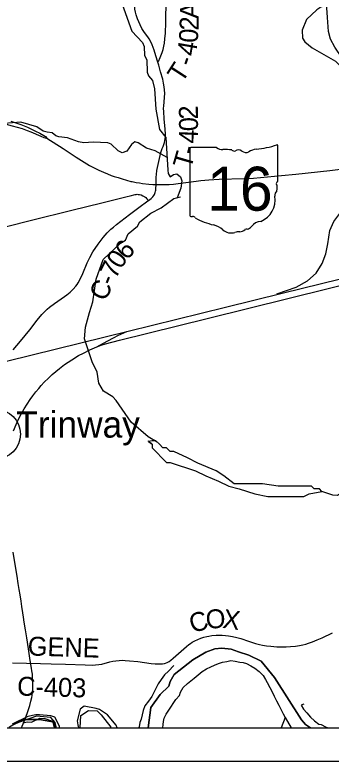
# Model space of a CAD drawing. Extents: x 0 to 34, y 0 to 22.
# Drawn here: x 6.577 to 7.523, y 14 to 16.238 of the extents above; entities that cross this region are included whole.
import ezdxf

# ---------------------------------------------------------------- set-up
doc = ezdxf.new("R2010")
doc.units = 0
for name, color, linetype in [('GM_X_Corporation', 7, 'Continuous'), ('GM_X_County_Road', 7, 'Continuous'), ('GM_X_County_Road_Text', 7, 'Continuous'), ('GM_X_Major_River', 7, 'Continuous'), ('GM_X_Minor_Lake', 7, 'Continuous'), ('GM_X_Minor_River', 7, 'Continuous'), ('GM_X_Rail_Line', 7, 'Continuous'), ('GM_X_State_Location', 7, 'Continuous'), ('GM_X_State_Route', 7, 'Continuous'), ('GM_X_State_Shield', 7, 'Continuous'), ('GM_X_Township_Road', 7, 'Continuous'), ('GM_X_Township_Road_Text', 7, 'Continuous'), ('GM_X_Unincorporated', 7, 'Continuous'), ('GM_X_Unincorporated_Text', 7, 'Continuous'), ('SH_Data', 7, 'Continuous')]:
    doc.layers.add(name, color=color, linetype=linetype)

msp = doc.modelspace()

# ---------------------------------------------------------------- linework, layer by layer
at = {"layer": 'GM_X_Corporation'}
for points in [[(2.1, 16.4477), (2.1, 14.1), (8.9, 14.1), (8.9, 16.2485)], [(6.5592, 14.1021), (6.5997, 14.1245), (6.6505, 14.1251), (6.6949, 14.1163), (6.697, 14.1), (6.7725, 14.1), (6.774, 14.1364), (6.7969, 14.1517), (6.8227, 14.1507), (6.8352, 14.1392), (6.8644, 14.1013), (6.8648, 14.1), (6.9761, 14.1), (6.9834, 14.1608), (7.0113, 14.1998), (7.0381, 14.2242), (7.0417, 14.2386), (7.0533, 14.2599), (7.11, 14.3032), (7.1487, 14.3269), (7.1751, 14.337), (7.1967, 14.339), (7.2239, 14.3354), (7.246, 14.328), (7.277, 14.3176), (7.3146, 14.2996), (7.3543, 14.251), (7.4347, 14.1238), (7.4466, 14.1098), (7.4614, 14.1), (7.7766, 14.1)], [(5.9661, 14.1), (6.701, 14.1), (6.6974, 14.116), (6.6847, 14.1303), (6.6414, 14.1352), (6.5874, 14.1159), (6.568, 14.1068)], [(5.9669, 14.1), (6.697, 14.1), (6.6949, 14.1163), (6.6505, 14.1251), (6.5997, 14.1245), (6.5592, 14.1021)]]:
    msp.add_lwpolyline(points, dxfattribs=at)
msp.add_lwpolyline([(6.9761, 14.1), (7.4614, 14.1), (7.4466, 14.1098), (7.4347, 14.1238), (7.3543, 14.251), (7.3146, 14.2996), (7.277, 14.3176), (7.246, 14.328), (7.2239, 14.3354), (7.1967, 14.339), (7.1751, 14.337), (7.1487, 14.3269), (7.11, 14.3032), (7.0533, 14.2599), (7.0417, 14.2386), (7.0381, 14.2242), (7.0113, 14.1998), (6.9834, 14.1608)], close=True, dxfattribs=at)
at = {"layer": 'GM_X_County_Road'}
for points in [[(6.9773, 15.6816), (6.9848, 15.6877), (6.9894, 15.6923), (6.9925, 15.6961), (6.9945, 15.6991), (6.9956, 15.7021), (6.9968, 15.7054), (6.9979, 15.7096), (6.9984, 15.712), (6.999, 15.7169), (6.9995, 15.7293)], [(6.0536, 15.5319), (6.1339, 15.5298), (6.1992, 15.5286), (6.2241, 15.529), (6.2458, 15.5306), (6.2674, 15.5335), (6.2888, 15.5378), (6.3973, 15.5647), (6.6263, 15.6221), (6.7469, 15.6522), (6.8373, 15.6746), (6.913, 15.6935)], [(6.913, 15.6935), (6.9217, 15.6956), (6.9368, 15.6992), (6.9399, 15.6997), (6.9429, 15.7), (6.9461, 15.6999), (6.9499, 15.6993), (6.9547, 15.698), (6.9603, 15.6957), (6.9655, 15.6927), (6.9684, 15.6902), (6.9722, 15.6867), (6.9773, 15.6816)], [(6.5714, 15.2339), (6.5935, 15.2599), (6.6212, 15.2932), (6.6438, 15.3228), (6.6576, 15.3396), (6.662, 15.3446), (6.6684, 15.3508), (6.6734, 15.3553), (6.6801, 15.3611), (6.6951, 15.3722), (6.7256, 15.3935), (6.7324, 15.3987), (6.7425, 15.407), (6.7514, 15.4155), (6.7594, 15.4248), (6.7629, 15.4296), (6.7664, 15.4349), (6.7723, 15.4457), (6.78, 15.4626), (6.7931, 15.4941), (6.8013, 15.5109), (6.8106, 15.5271), (6.8263, 15.5502), (6.8412, 15.5701), (6.8534, 15.5842), (6.8583, 15.5894), (6.8645, 15.5952), (6.8716, 15.6012), (6.881, 15.6093), (6.9201, 15.6399), (6.9474, 15.6604), (6.9753, 15.68), (6.9773, 15.6816)], [(6.57, 14.295), (6.6539, 14.2926), (6.6849, 14.2917), (6.7285, 14.2904), (6.7875, 14.2884), (6.8092, 14.2879), (6.8185, 14.2882), (6.8277, 14.2893), (6.8367, 14.2911), (6.8608, 14.2974), (6.8699, 14.2995), (6.8792, 14.3011), (6.8885, 14.302), (6.8979, 14.3023), (6.9073, 14.3021), (6.9197, 14.3011), (6.9444, 14.2982), (6.9845, 14.293), (6.9969, 14.2919), (7.0061, 14.2914), (7.0123, 14.2915), (7.0184, 14.292), (7.0244, 14.2931), (7.0274, 14.2939), (7.033, 14.2961), (7.0384, 14.299), (7.0435, 14.3024), (7.0507, 14.3082), (7.0903, 14.3432), (7.0975, 14.3492), (7.1025, 14.353), (7.1077, 14.3564), (7.116, 14.361), (7.1245, 14.3649), (7.1332, 14.3683), (7.1421, 14.3713), (7.1512, 14.3738), (7.1573, 14.375), (7.1666, 14.3763), (7.1791, 14.3773), (7.1884, 14.3777), (7.1978, 14.3776), (7.2072, 14.3771), (7.2165, 14.376), (7.2288, 14.3739), (7.241, 14.3711), (7.253, 14.3676), (7.2766, 14.3598), (7.2972, 14.353), (7.3091, 14.3495), (7.3182, 14.3475), (7.3304, 14.3455), (7.3427, 14.3442), (7.3613, 14.343), (7.3768, 14.3425), (7.3892, 14.3427), (7.4016, 14.3435), (7.417, 14.3451), (7.4293, 14.3469), (7.4384, 14.3487), (7.4474, 14.3509), (7.4563, 14.3535), (7.468, 14.3576), (7.4823, 14.3635), (7.4965, 14.3697), (7.5273, 14.3847)]]:
    msp.add_lwpolyline(points, dxfattribs=at)
at = {"layer": 'GM_X_Major_River'}
for points in [[(7.0528, 14.2867), (7.0364, 14.27), (7.0251, 14.2582), (7.0149, 14.2449), (7.0062, 14.2312), (7.0006, 14.2217), (6.9942, 14.2073), (6.9863, 14.194), (6.9769, 14.1796), (6.9663, 14.1655), (6.9607, 14.1515), (6.9577, 14.1386), (6.9551, 14.1257), (6.951, 14.1158), (6.9487, 14.1025), (6.9483, 14.1)], [(7.0589, 14.1845), (7.0693, 14.1964), (7.0725, 14.2066), (7.0807, 14.2208), (7.0934, 14.2331), (7.1031, 14.2408), (7.1132, 14.2482), (7.1252, 14.2589), (7.1371, 14.269), (7.1503, 14.2767), (7.1634, 14.283), (7.1747, 14.2877), (7.1864, 14.2928), (7.1981, 14.2967), (7.2113, 14.2984), (7.2234, 14.3016), (7.2366, 14.2995), (7.2503, 14.2971), (7.2605, 14.2953), (7.27, 14.2924), (7.2834, 14.2858), (7.2956, 14.2788), (7.3079, 14.2691), (7.3198, 14.2571), (7.3271, 14.2451), (7.3326, 14.2353), (7.34, 14.2206), (7.3466, 14.2074), (7.3528, 14.195), (7.3598, 14.1811), (7.3672, 14.1675), (7.3735, 14.1559), (7.3801, 14.1416), (7.3863, 14.1303), (7.3933, 14.1183), (7.4041, 14.1)], [(7.0199, 14.1), (7.0206, 14.1096), (7.0221, 14.119), (7.024, 14.1289), (7.0296, 14.1407), (7.0379, 14.1528), (7.0589, 14.1845)], [(7.4418, 14.1709), (7.4342, 14.1677), (7.4412, 14.1557), (7.4512, 14.1445), (7.4616, 14.1317), (7.4743, 14.1205), (7.4869, 14.1112)], [(7.4869, 14.1112), (7.4941, 14.1098), (7.5067, 14.1032), (7.5141, 14.1)]]:
    msp.add_lwpolyline(points, dxfattribs=at)
at = {"layer": 'GM_X_Minor_Lake'}
for points in [[(7.0526, 14.9285), (7.0418, 14.9285), (7.031, 14.9393), (7.0202, 14.9393), (7.0094, 14.9501), (6.9986, 14.9609), (6.9878, 14.9609), (6.977, 14.9587)], [(6.977, 14.9587), (6.977, 14.9609), (6.9878, 14.9501), (6.9878, 14.9393), (6.9986, 14.9285), (7.0202, 14.9069), (7.031, 14.8961), (7.0418, 14.8961)], [(6.977, 14.9587), (6.9878, 14.9501), (6.9878, 14.9393), (6.9986, 14.9285), (7.0202, 14.9069), (7.031, 14.8961), (7.0418, 14.8961)], [(7.4961, 14.8089), (7.4884, 14.8166), (7.4729, 14.8166), (7.4652, 14.8244), (7.442, 14.8244), (7.4265, 14.8244), (7.4033, 14.8244), (7.3647, 14.8244), (7.3182, 14.8321), (7.2796, 14.8321), (7.2332, 14.8321), (7.2022, 14.8553), (7.179, 14.8708), (7.1249, 14.894), (7.0939, 14.9095), (7.0526, 14.9285)], [(7.0418, 14.8961), (7.1172, 14.8708), (7.1481, 14.8553), (7.1868, 14.8399), (7.2177, 14.8244), (7.2486, 14.8166), (7.295, 14.8012), (7.3337, 14.7934), (7.3879, 14.7934), (7.4111, 14.7934), (7.4343, 14.7934), (7.442, 14.7934), (7.4575, 14.8012), (7.4961, 14.8089)]]:
    msp.add_lwpolyline(points, dxfattribs=at)
at = {"layer": 'GM_X_Minor_River'}
msp.add_line((7.3861, 14.1307), (7.3736, 14.1), dxfattribs=at)
for points in [[(6.8721, 16.3002), (6.8979, 16.2707), (6.927, 16.1892), (6.9589, 16.1552), (6.9643, 16.1431), (6.9652, 16.1161), (6.972, 16.1036), (6.9726, 16.0668), (6.9772, 16.0558), (6.989, 16.0415), (6.9944, 16.0164), (6.9984, 15.9558), (7.0093, 15.8947), (7.0291, 15.8709), (7.0344, 15.7726), (7.036, 15.7624), (7.0421, 15.7522)], [(7.5143, 16.286), (7.5155, 16.2768), (7.5069, 16.2654), (7.4929, 16.2615), (7.4805, 16.2539), (7.4497, 16.2244), (7.4371, 16.1929), (7.4374, 16.1682), (7.4446, 16.1573), (7.4671, 16.1392), (7.537, 16.0999), (7.548, 16.0886), (7.5657, 16.0595), (7.5876, 16.0115), (7.5901, 15.9831), (7.5944, 15.971), (7.5938, 15.9486), (7.6112, 15.9063), (7.6182, 15.876)], [(7.0323, 15.8104), (6.9971, 15.8306), (6.9709, 15.8388), (6.9462, 15.8543), (6.9356, 15.8573), (6.9258, 15.8497), (6.9123, 15.8299), (6.8975, 15.8245), (6.8861, 15.8306), (6.8652, 15.8502), (6.8554, 15.854), (6.8111, 15.8565), (6.7827, 15.8545), (6.7668, 15.8571), (6.7338, 15.8699), (6.7084, 15.8728), (6.6989, 15.8758), (6.6879, 15.8849), (6.6731, 15.886), (6.661, 15.8897), (6.6424, 15.9026), (6.5943, 15.9161), (6.5447, 15.9125)], [(7.042, 15.7523), (7.0517, 15.7598), (7.0615, 15.7614), (7.0729, 15.7528), (7.0768, 15.7403), (7.0739, 15.7186), (7.0622, 15.6896)], [(7.003, 14.9566), (6.9762, 14.9723), (6.9249, 15.0161), (6.8802, 15.0819), (6.8703, 15.0929), (6.8418, 15.1098), (6.8277, 15.134), (6.8233, 15.1667), (6.8077, 15.1973), (6.7854, 15.2663), (6.7882, 15.3016), (6.8002, 15.3452), (6.8102, 15.3775), (6.8198, 15.4451), (6.8415, 15.5044), (6.8928, 15.5535), (6.9076, 15.5627), (6.9162, 15.5817), (6.9438, 15.6046), (6.9509, 15.6175), (6.9838, 15.6431), (7.0151, 15.6599), (7.0522, 15.6874), (7.0726, 15.692)], [(7.9344, 14.622), (7.885, 14.6124), (7.8459, 14.5901), (7.8221, 14.5816), (7.8097, 14.5815), (7.7853, 14.5973), (7.7621, 14.6191), (7.7011, 14.7222), (7.681, 14.7759), (7.6743, 14.8059), (7.6663, 14.8187), (7.6553, 14.8273), (7.628, 14.8309), (7.5952, 14.825), (7.5662, 14.8127), (7.5425, 14.7962), (7.5292, 14.7973), (7.4961, 14.8089)], [(6.883, 14.1), (6.8799, 14.1081), (6.8544, 14.1384), (6.8305, 14.1543), (6.8199, 14.158), (6.7846, 14.1651), (6.7718, 14.156), (6.7633, 14.1206), (6.7648, 14.1085), (6.7677, 14.1)], [(6.7105, 14.1), (6.7103, 14.1045), (6.6963, 14.1317), (6.6847, 14.1359), (6.65, 14.1392), (6.6398, 14.1388), (6.6152, 14.1338), (6.5691, 14.1105)], [(6.6009, 14.1152), (6.6145, 14.1179), (6.6266, 14.1168), (6.6516, 14.129), (6.6663, 14.1275), (6.6891, 14.1196), (6.6941, 14.1)]]:
    msp.add_lwpolyline(points, dxfattribs=at)
at = {"layer": 'GM_X_Rail_Line'}
for points in [[(7.3608, 15.4019), (7.4193, 15.4215), (7.4527, 15.4405), (7.4789, 15.4634), (7.4972, 15.4929), (7.5077, 15.5217), (7.5136, 15.5518), (7.5201, 15.5911), (7.5319, 15.6186), (7.562, 15.6585), (7.6072, 15.7168), (7.6249, 15.7462), (7.6353, 15.7789), (7.6425, 15.8254), (7.6491, 15.8922), (7.6484, 15.94), (7.638, 15.9779), (7.6236, 16.0048), (7.5994, 16.0454), (7.5352, 16.1416), (7.5215, 16.1652), (7.5156, 16.1887), (7.513, 16.23), (7.5097, 16.2732)], [(4.7232, 14.7487), (4.8596, 14.7823), (5.0004, 14.8171), (5.0735, 14.8354), (5.1763, 14.8606), (5.27, 14.8838), (5.3976, 14.9152), (5.5295, 14.9475), (5.6419, 14.9754), (5.7924, 15.0128), (5.9194, 15.0442), (6.0332, 15.0721), (6.178, 15.108), (6.2632, 15.1289), (6.9157, 15.2894), (7.2078, 15.3612), (7.3771, 15.4031), (8.007, 15.5582), (8.6833, 15.725), (8.9, 15.7782)], [(6.5729, 14.9905), (6.5805, 15.0097), (6.587, 15.024), (6.5968, 15.0428), (6.6046, 15.0568), (6.6133, 15.0708), (6.6226, 15.085), (6.6306, 15.096), (6.6392, 15.1071), (6.6481, 15.1178), (6.6555, 15.1263), (6.6649, 15.1365), (6.6772, 15.1489), (6.6888, 15.1598), (6.7101, 15.1777), (6.7252, 15.1892), (6.7475, 15.204), (6.7676, 15.2162), (6.7824, 15.2239), (6.8016, 15.2338), (6.8218, 15.2428), (6.8347, 15.2477), (6.8482, 15.2518), (6.8903, 15.2624), (7.1524, 15.3272), (8.006, 15.5393)], [(6.8218, 15.2428), (6.8534, 15.2594), (6.8738, 15.2708), (6.8851, 15.2768), (6.9118, 15.2884)], [(6.5964, 14.1), (6.6081, 14.1292), (6.6169, 14.1518), (6.6215, 14.1668), (6.6247, 14.1796), (6.6271, 14.1905), (6.6283, 14.1972), (6.6291, 14.2068), (6.63, 14.2162), (6.6303, 14.2281), (6.6303, 14.2397), (6.6298, 14.2508), (6.629, 14.2603), (6.6275, 14.2709), (6.6264, 14.2791), (6.6228, 14.302), (6.6174, 14.3365), (6.6122, 14.3696), (6.6086, 14.3932), (6.6049, 14.4163), (6.6026, 14.4313), (6.6005, 14.4442), (6.5977, 14.4633), (6.5951, 14.4801), (6.5921, 14.4986), (6.5895, 14.5148), (6.5865, 14.5331), (6.5833, 14.5544), (6.5777, 14.5894), (6.5718, 14.6263)]]:
    msp.add_lwpolyline(points, dxfattribs=at)
at = {"layer": 'GM_X_State_Route'}
for points in [[(6.4629, 15.9199), (6.467, 15.9198), (6.4857, 15.9189), (6.5013, 15.9176), (6.5168, 15.9158), (6.5353, 15.9129), (6.5507, 15.91), (6.5689, 15.9059), (6.584, 15.9017), (6.5989, 15.897), (6.6136, 15.8918), (6.6244, 15.8875), (6.6548, 15.8741), (6.6635, 15.8707), (6.6671, 15.8696), (6.6727, 15.8688)], [(6.565, 15.919), (6.5798, 15.9144), (6.5943, 15.9091), (6.6144, 15.901), (6.6285, 15.8947), (6.6387, 15.8897), (6.6512, 15.8837), (6.6639, 15.8767), (6.668, 15.8735), (6.6727, 15.8688)], [(7.4176, 15.7609), (7.5201, 15.7717), (7.5756, 15.7788), (7.637, 15.7883), (7.692, 15.7985), (7.9267, 15.8452), (8.0334, 15.8665), (8.2801, 15.9162), (8.3025, 15.9204), (8.329, 15.9252), (8.3566, 15.929), (8.3937, 15.9328), (8.4072, 15.9338), (8.4297, 15.9345), (8.4416, 15.9347), (8.465, 15.9344), (8.4898, 15.9336), (8.522, 15.9311)], [(6.6727, 15.8688), (6.7217, 15.8371), (6.7605, 15.8111), (6.7763, 15.8011), (6.8004, 15.7868), (6.814, 15.7793), (6.8279, 15.7723), (6.8421, 15.766), (6.8537, 15.7614), (6.8654, 15.7569), (6.8738, 15.7539), (6.8857, 15.7501), (6.898, 15.7461), (6.9243, 15.7387), (6.9278, 15.738), (6.9402, 15.7357), (6.95, 15.7342)], [(7.1191, 15.7393), (7.1331, 15.7412), (7.1578, 15.7438), (7.1887, 15.7456), (7.2633, 15.7471), (7.2913, 15.7485), (7.3748, 15.7564), (7.4176, 15.7609)], [(6.95, 15.7342), (6.9588, 15.7328), (6.9775, 15.7307), (6.99, 15.7297), (6.9995, 15.7293)], [(6.9995, 15.7293), (7.0209, 15.7293), (7.0383, 15.7298), (7.0514, 15.7308), (7.0653, 15.732), (7.1191, 15.7393)]]:
    msp.add_lwpolyline(points, dxfattribs=at)
at = {"layer": 'GM_X_State_Shield'}
for p, q in [((7.1009, 15.837), (7.1009, 15.6368)), ((7.1807, 15.8404), (7.1035, 15.8404)), ((7.3645, 15.7407), (7.3645, 15.8454)), ((7.3645, 15.7407), (7.3645, 15.7407))]:
    msp.add_line(p, q, dxfattribs=at)
for centre, radius, start, end in [((7.2706, 16.1132), 0.2796, 275.8445, 288.9065), ((7.3616, 15.8458), 0.00294, 351.8621, 97.738), ((7.1039, 15.8374), 0.00305, 98.1301, 188.1301), ((7.1991, 15.8636), 0.0296, 231.6195, 271.1119), ((7.2089, 15.7281), 0.1064, 80.4867, 94.9883), ((7.233, 15.8384), 0.00855, 219.7921, 297.1024), ((7.2456, 15.8153), 0.0178, 54.4667, 119.1411), ((7.2685, 15.847), 0.0214, 233.8562, 294.8282), ((7.3063, 15.7793), 0.0563, 97.3462, 120.7689), ((7.3639, 15.733), 0.00454, 107.944, 210.337), ((7.3614, 15.7403), 0.00314, 289.6038, 7.7341), ((7.335, 15.7198), 0.0273, 340.033, 23.6496), ((7.2863, 15.6835), 0.0699, 292.3089, 8.9858), ((7.3751, 15.6969), 0.0198, 136.8065, 186.9296), ((7.1039, 15.6364), 0.00308, 171.9584, 258.3066), ((7.1044, 15.6569), 0.0235, 267.339, 280.6039), ((7.1092, 15.6253), 0.00848, 29.7484, 93.2717), ((7.2163, 15.8051), 0.2019, 240.4129, 257.1985), ((7.1561, 15.5469), 0.0632, 47.1842, 75.836), ((7.2672, 15.6174), 0.0226, 282.8732, 323.2771), ((7.3158, 15.5807), 0.0383, 94.4031, 142.5768), ((7.2244, 15.6243), 0.0401, 230.7004, 286.2918), ((7.2476, 15.5551), 0.0329, 85.6951, 111.2099), ((7.2505, 15.6093), 0.0214, 268.777, 315.5493), ((7.2698, 15.5899), 0.00601, 65.7517, 132.6484)]:
    msp.add_arc(centre, radius, start, end, dxfattribs=at)
at = {"layer": 'GM_X_Township_Road'}
for points in [[(7.0045, 16.0968), (6.9987, 16.1157), (6.9934, 16.1324), (6.9873, 16.1489), (6.9824, 16.1597), (6.9784, 16.1661), (6.9745, 16.1723), (6.9648, 16.185), (6.9569, 16.197), (6.9515, 16.2086), (6.9441, 16.2264), (6.9419, 16.2322), (6.9401, 16.238), (6.938, 16.2465), (6.9362, 16.2552), (6.9349, 16.2683), (6.9328, 16.2899), (6.9311, 16.3024)], [(7.0045, 16.0968), (7.006, 16.0983), (7.0077, 16.1009), (7.0092, 16.1034), (7.0102, 16.1052), (7.0142, 16.1155), (7.0181, 16.1257), (7.0209, 16.1344), (7.023, 16.1449), (7.0244, 16.1531), (7.026, 16.1668), (7.0277, 16.1834), (7.0281, 16.1954), (7.0286, 16.2039), (7.0286, 16.2223), (7.0292, 16.2376), (7.0296, 16.2625), (7.0299, 16.2749), (7.0301, 16.2843), (7.0305, 16.299)], [(7.0178, 15.837), (7.0181, 15.8379), (7.0203, 15.8435), (7.0227, 15.8493), (7.0247, 15.8552), (7.0262, 15.8613), (7.0271, 15.8676), (7.0274, 15.8739), (7.0274, 15.8801), (7.0264, 15.8957), (7.0236, 15.9266), (7.0223, 15.9482), (7.0218, 15.9573), (7.0223, 15.9656), (7.0235, 15.9763), (7.025, 15.9915), (7.0255, 16.0026), (7.0248, 16.0132), (7.0238, 16.0226), (7.0218, 16.0335), (7.0196, 16.0451), (7.0129, 16.0677), (7.0075, 16.0877), (7.0045, 16.0968)], [(6.9995, 15.7293), (6.9993, 15.7375), (6.9994, 15.7435), (6.9997, 15.7511), (7.0004, 15.7594), (7.0019, 15.7717), (7.0034, 15.7808), (7.0053, 15.7899), (7.0142, 15.8258), (7.0159, 15.8317), (7.0178, 15.837)]]:
    msp.add_lwpolyline(points, dxfattribs=at)
at = {"layer": 'GM_X_Unincorporated'}
msp.add_circle((6.519, 14.9806), 0.0744, dxfattribs=at)
at = {"layer": 'SH_Data'}
for p, q in [((2.1, 14.1), (8.9, 14.1)), ((2, 14), (9, 14))]:
    msp.add_line(p, q, dxfattribs=at)

# ---------------------------------------------------------------- texts
at = {"layer": 'GM_X_County_Road_Text'}
for s, height, rotation, p in [('6', 0.0568, 47.4109, (6.912, 15.5003)), ('0', 0.0568, 55.2548, (6.8933, 15.4731)), ('7', 0.0568, 63.94, (6.8791, 15.4437)), ('-', 0.0568, 67.7341, (6.8706, 15.423)), ('C', 0.0568, 61.7119, (6.8457, 15.376)), ('C', 0.0568, 17.9042, (7.1092, 14.3828)), ('O', 0.0568, 3.8497, (7.15, 14.3965)), ('X', 0.0568, 351.9194, (7.1967, 14.3999)), ('GENE', 0.05682, 358.1876, (6.6145, 14.3169)), ('C-403', 0.05682, 358.3484, (6.5829, 14.1967))]:
    msp.add_text(s, height=height, rotation=rotation, dxfattribs=at).set_placement(p)
at = {"layer": 'GM_X_State_Location'}
for s in ['s', 'r']:
    msp.add_text(s, height=0.000189, dxfattribs=at).set_placement((7.2297, 15.7236))
msp.add_text('16', height=0.000189, rotation=0, dxfattribs=at).set_placement((7.182, 15.7098))
at = {"layer": 'GM_X_State_Shield'}
msp.add_text('16', height=0.13184, dxfattribs=at).set_placement((7.1524, 15.6509))
at = {"layer": 'GM_X_Township_Road_Text'}
for s, rotation, p in [('A', 88.8139, (7.1273, 16.2259)), ('2', 88.4771, (7.1264, 16.1906)), ('0', 86.1246, (7.1239, 16.1531)), ('4', 80.0698, (7.117, 16.1121)), ('T', 57.0647, (7.0772, 16.0314)), ('-', 70.757, (7.1068, 16.0803)), ('2', 90.6276, (7.1249, 15.9247)), ('0', 90.5144, (7.1252, 15.8896)), ('4', 87.731, (7.1238, 15.8516)), ('T', 73.8356, (7.1034, 15.7735)), ('-', 74.6026, (7.1154, 15.8151))]:
    msp.add_text(s, height=0.0568, rotation=rotation, dxfattribs=at).set_placement(p)
at = {"layer": 'GM_X_Unincorporated_Text'}
msp.add_text('Trinway', height=0.07898, rotation=0, dxfattribs=at).set_placement((6.5812, 14.9703))

doc.saveas('drawing.dxf')
